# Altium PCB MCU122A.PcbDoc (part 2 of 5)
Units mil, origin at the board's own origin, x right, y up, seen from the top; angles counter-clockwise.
Board outline 4950 x 3450 mil, 4 copper layers (Top Layer, Signal Layer 1, Signal Layer 2, Bottom Layer), stack 60 mil thick; 257 components, 158 nets, 848 pads, 1971 vias.
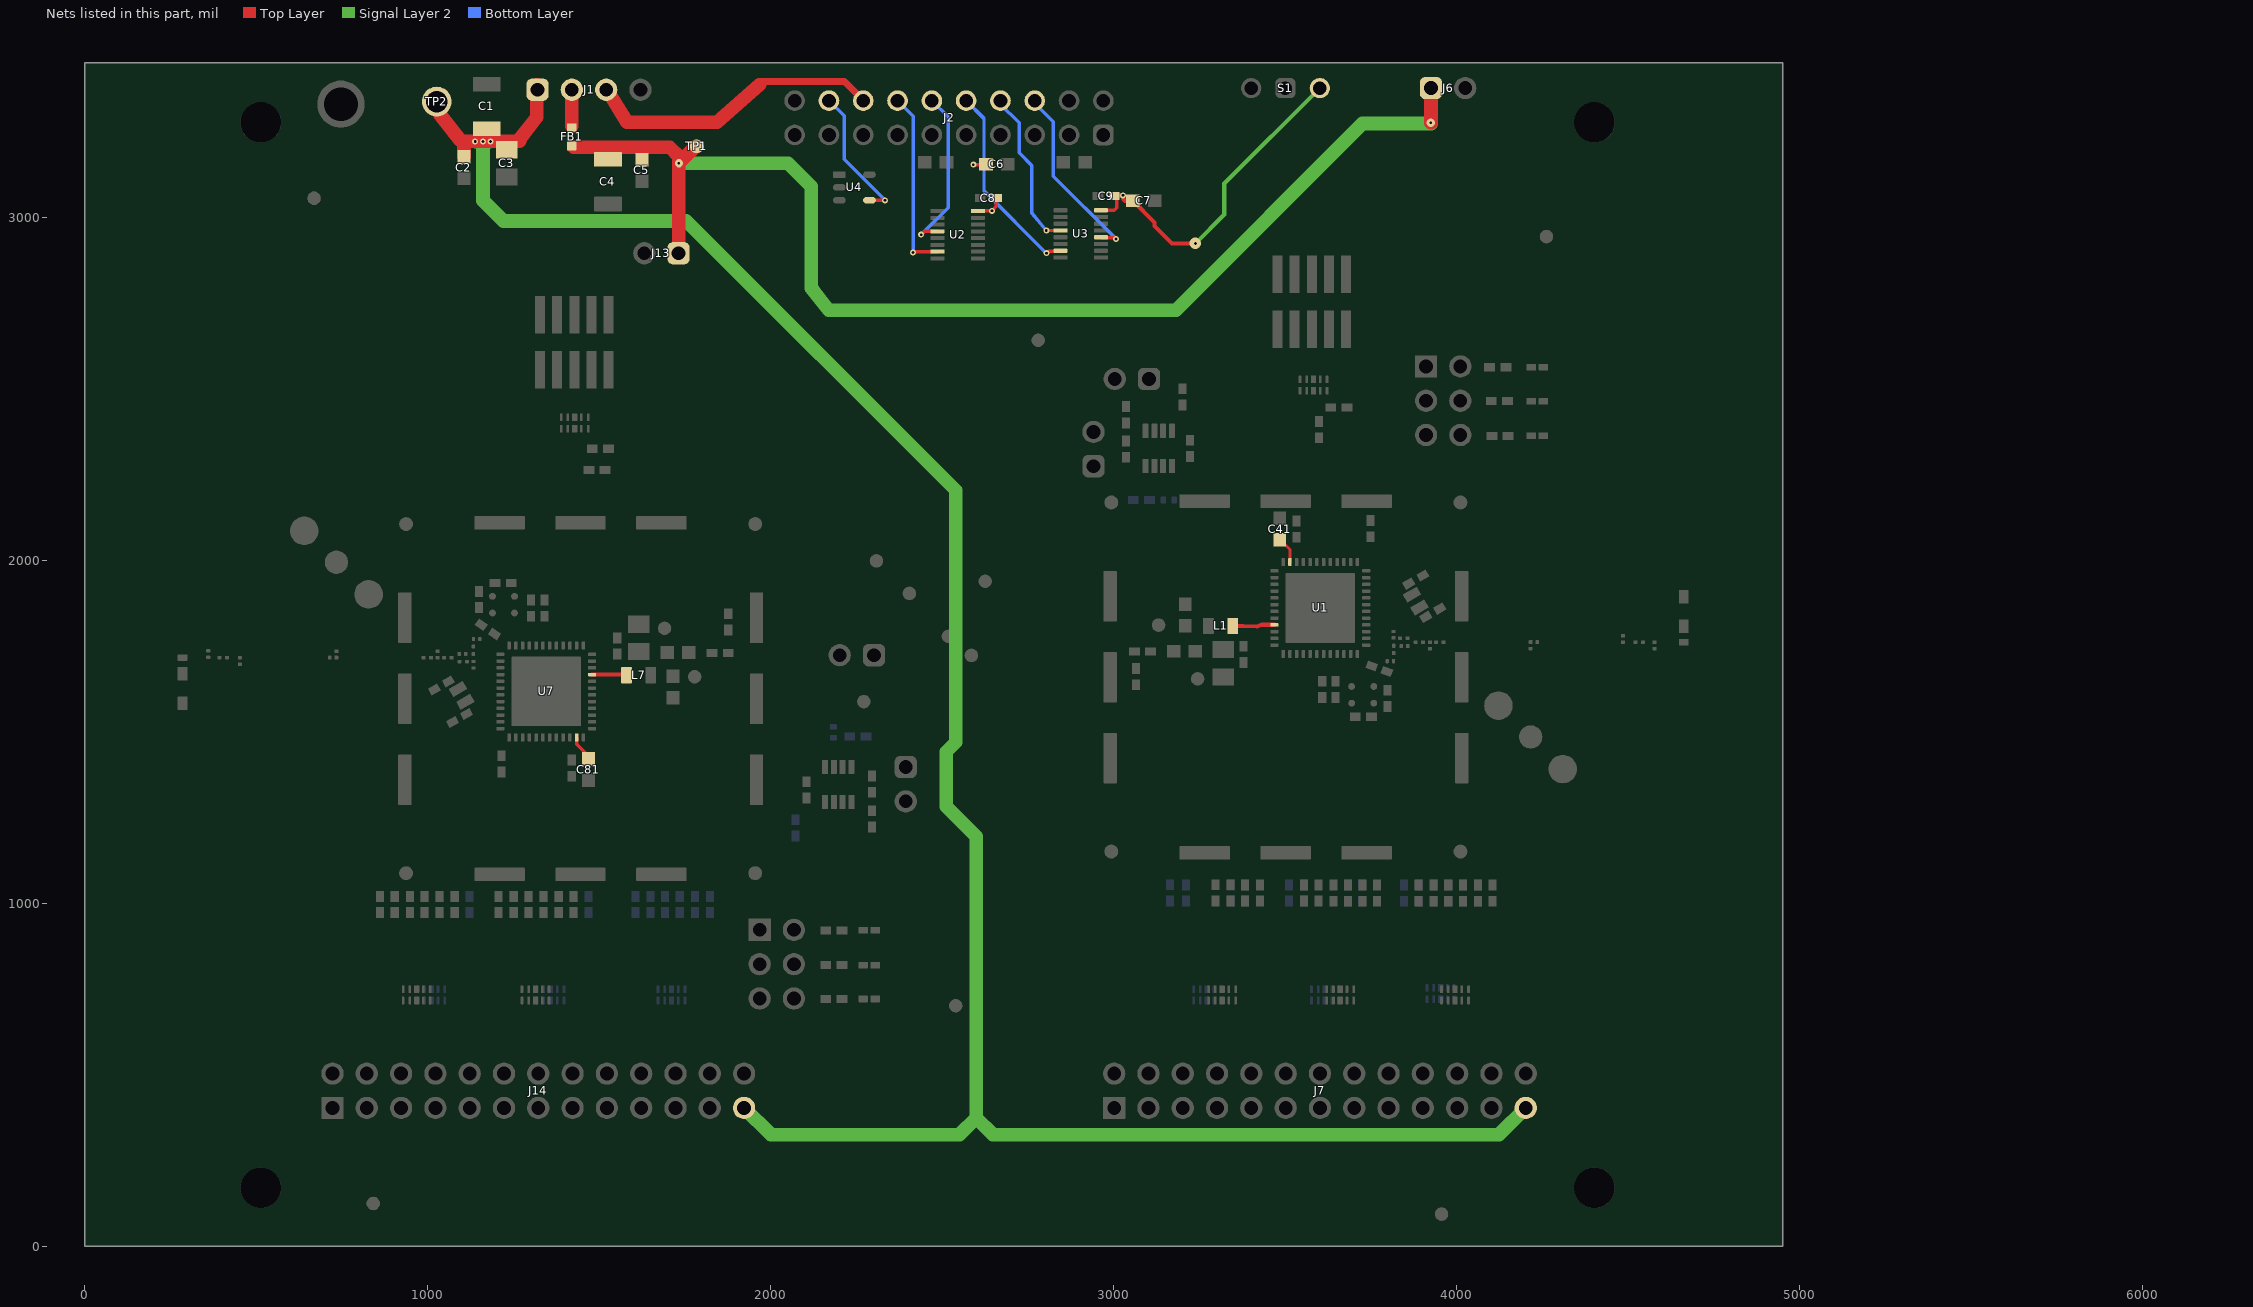
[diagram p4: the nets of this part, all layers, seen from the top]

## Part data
ANT1 ANT2: library part CMP-0091830-1, "2.4-GHz Inverted F Antenna", Manufacturer="Texas Instruments", Operating Temperature Range=to
C1 C4: library part CMP-0037171-1, "Ceramic Capacitor for Automotive 10uF ±20% 25VDC X7R 1210 Embossed T/R", Manufacturer=Murata, Operating Temperature Range="-55°C to +125°C", TempCo=15%, Temperature Characteristic=X7R, Tolerance_%=20%, ValueDisplayed=10uF
C2 C5 C6 C7 C10 C11 C41 C81: library part CMP-0007136-5, "CAP, CERM, 1 uF, 16 V, +/- 10%, X7R, AEC-Q200 Grade 1, 0603", Cap_Case=0603, Manufacturer=MuRata, Supplier Part Number 1=490-5241-6-ND, TempCo=X7R, Tolerance_%=10%, Value1=Unknown, Value2=16V, ValueDisplayed=1uF
C3 C21 C61: library part CMP-0008015-1, "CAP, CERM, 22 uF, 6.3 V, +/- 20%, X7T, AEC-Q200 Grade 1, 0805", Cap_Case=0805, Manufacturer=MuRata, TempCo=X7T, Tolerance_%=20%, Value1=Unknown, Value2=6.3V, ValueDisplayed=22uF
C8 C9 C22 C23 C24 C25 C27 C28 C48 C50 C62 C63 C64 C65 C67 C68 C88 C90: library part CMP-0006350-2, "CAP, CERM, 0.1 uF, 10 V, +/- 10%, X7R, AEC-Q200 Grade 1, 0402", Cap_Case=0402, Manufacturer=MuRata, Supplier Part Number 1=81-GCM155R71A104K5D, TempCo=X7R, Tolerance_%=10%, Value1=Unknown, Value2=10V, ValueDisplayed=0.1uF
C12 C13 C14 C15 C16 C17 C18 C19 C20 C29 C30 C31 C32 C33 C34 C52 C53 C54 C55 C56 C57 C58 C59 C60 C69 C70 C71 C72 C73 C74: library part CMP-0006350-2, "CAP, CERM, 0.1 uF, 10 V, +/- 10%, X7R, AEC-Q200 Grade 1, 0402", Cap_Case=0402, Manufacturer=MuRata, Supplier Part Number 1=81-GCM155R71A104K5D, TempCo=X7R, Tolerance_%=10%, Value1=Unknown, Value2=10V, ValueDisplayed=DNP
C26 C66: library part CMP-0064940-5, "CAP, CERM, 22 uF, 4 V,+/- 20%, X5R, AEC-Q200 Grade 3, 0603", Cap_Case=0603, Manufacturer="Taiyo Yuden", Supplier Part Number 1=587-3262-1-ND, TempCo=X5R, Tolerance_%=20%, Value1=Unknown, Value2=4V, ValueDisplayed=22uF
C35 C36 C75 C76: library part CMP-0085816-1, "CAP, CERM, 12 pF, 50 V,+/- 5%, C0G/NP0, AEC-Q200 Grade 1, 0402", Cap_Case=0402, Manufacturer=MuRata, TempCo=C0G/NP0, Tolerance_%=5%, Value2=50V, ValueDisplayed=12pF
C37 C38 C77 C78: library part CMP-0085816-1, "CAP, CERM, 12 pF, 50 V,+/- 5%, C0G/NP0, AEC-Q200 Grade 1, 0402", Cap_Case=0402, Manufacturer=MuRata, TempCo=C0G/NP0, Tolerance_%=5%, Value2=50V, ValueDisplayed=DNP
C39 C46 C79 C86: library part CMP-0037173-1, "1pF ±0.1pF 50V Ceramic Capacitor C0G 0201 (0603 Metric)", Manufacturer=Murata, Operating Temperature Range="-55°C to +125°C", TempCo=30ppm/°C, Temperature Characteristic=C0G, ValueDisplayed=DNP
C40 C43 C80 C83: library part CMP-0120430-1, "High Q Chip Multilayer Ceramic Capacitors for Automotive 12pF ±2% 50Vdc 0201", Manufacturer=Murata, Operating Temperature Range="-25°C to +125°C", TempCo=30ppm/°C, Temperature Characteristic=C0G, Tolerance_%=2%, ValueDisplayed=12pF
C42 C44 C47 C82 C84 C87: library part CMP-0120431-1, "1pF ±0.05pF 50V Ceramic Capacitor C0G 0201 (0603 Metric)", Manufacturer=Murata, Operating Temperature Range="-55°C to +125°C", TempCo=30ppm/°C, Temperature Characteristic=C0G, ValueDisplayed=1pF
C45 C85: library part CMP-0124488-1, "Cap Ceramic 0.7pF ±0.05pF 50V C0G 0201 AECQ200", Manufacturer=Murata, Operating Temperature Range="-55°C to +125°C", TempCo=30ppm/°C, Temperature Characteristic=C0G, ValueDisplayed=0.7pF
C49 C89: library part CMP-0120705-1, "Ceramic Capacitor for Automotive 47nF ±10% 25VDC X7R 0402 Paper T/R", Manufacturer=Murata, Operating Temperature Range="-55°C to +125°C", TempCo=15%, Temperature Characteristic=X7R, Tolerance_%=0.1%, ValueDisplayed=47nF
C51 C91: library part CMP-0006352-2, "CAP, CERM, 0.01 uF, 25 V, +/- 10%, X7R, 0402", Cap_Case=0402, Manufacturer=MuRata, Supplier Part Number 1=490-6043-2-ND, TempCo=X7R, Tolerance_%=10%, Value1=Unknown, Value2=25V, ValueDisplayed=0.01uF
D1 D4: library part CMP-0120353-1, "Green 525nm LED Indication - Discrete 2.65V 0402 (1005 Metric)", Color=Green, Digikey Part Number=754-2126-1-ND, Forward Current=2mA, Manufacturer=Kingbright, Mouser Part Number=604-APHHS1005LZGCK-V, Operating Temperature Range="-40°C to +85°C", Power_TotalModule=102.5mW
D2 D5: library part CMP-0120352-1, "LED Uni-Color SB. Orange 611nm 2-Pin SMD T/R", Color=Orange, Digikey Part Number=754-2124-1-ND, Forward Current=2mA, Manufacturer=Kingbright, Mouser Part Number=604-HHS1005LSECKJ4PF, Operating Temperature Range="-40°C to +85°C", Power_TotalModule=84mW
D3 D6: library part CMP-0120351-1, "Red 625nm LED Indication - Discrete 1.8V 0402 (1005 Metric)", Color=Red, Digikey Part Number=754-2123-1-ND, Forward Current=2mA, Manufacturer=Kingbright, Mouser Part Number=604-APHHS1005LSECKJ3, Operating Temperature Range="-40°C to +85°C", Power_TotalModule=84mW
FB1: library part CMP-0092703-1, "Chip Ferrite Bead, 0603, 1500Ω @ 100MHz, 0.5Ω, 25%, 500mA", Impedance At Frequency="1500Ω @ 100MHz", Manufacturer=Murata, Operating Temperature Range="-55°C to +125℃", Test Frequency=100MHz, Tolerance_%=25%
FB2 FB3: library part CMP-0080768-1, "Ferrite Bead, 1500 ohm @ 100 MHz, 0.5 A, 0603", Manufacturer=MuRata, Supplier Part Number 1=490-16502-1-ND, Value1="0.5 ohm", Value2=0.5A, ValueDisplayed="1500 ohm"
FID1 FID2 FID3 FID4 FID5 FID6 FID7 FID8 FID9 FID10 FID11 FID12: library part CMP-0077181-1, "Fiducial mark.  There is nothing to buy or mount.", Manufacturer=N/A
J1: library part CMP-0075409-2, "Header, 100mil, 4x1, Gold, TH", Color=Black, Current_A=6.3A, Manufacturer=Samtec, Supplier Part Number 1=SAM1029-04-ND, Voltage_V=550V
J2: library part CMP-0074634-1, "Receptacle, 2.54mm, 10x2, Gold, R/A, TH", Color=Black, Current_A=3A, Manufacturer="Sullins Connector Solutions", Supplier Part Number 1=S9205-ND, Voltage_V=1kV
J3 J10: library part CMP-0075406-2, "Header, 100mil, 3x2, Gold, TH", Color=Black, Current_A=6.3A, Manufacturer=Samtec, Supplier Part Number 1=SAM1028-03-ND, Voltage_V=550V
J4 J11: library part CMP-0035654-1, "SMA PCB Surface Mount Jack 50 Ohm", Dielectric Material=PTFE, Digikey Part Number=ARF2755-ND, Frequency_Fixed=18GHz, Manufacturer="Amphenol Connex", Mouser Part Number=523-132134-10, Operating Temperature Range="-65°C to +165°C"
J5 J12: library part CMP-0075670-2, "Header (Shrouded), 1.27mm, 5x2, Gold, SMT", Color=Black, Current_A=3.3A, Manufacturer=Samtec, Supplier Part Number 1=SAM8796-ND
J6 J8 J9 J13 J15 J16: library part CMP-0075405-3, "Header, 100mil, 2x1, Gold, TH", Color=Black, Current_A=6.3A, Manufacturer=Samtec, Supplier Part Number 1=SAM1029-02-ND, Voltage_V=550V
J7 J14: library part CMP-0075425-1, "Header, 100mil, 13x2, Gold, TH", Color=Black, Current_A=6.3A, Manufacturer=Samtec, Supplier Part Number 1=SAM1028-13-ND, Voltage_V=550V
L1 L7: library part CMP-0121210-1, "Shielded Multilayer Inductor 6.8uH ±20% 550mA 325mΩ AEC-Q200 SMD 0805", Manufacturer=TDK, Operating Temperature Range="-55°C to +125°C", Test Frequency=2MHz, Tolerance_%=20%
L2 L6 L8 L12: library part CMP-0090225-1, "Inductor 3.7nH, Size Code 0603 (0201), High Q, Wide Variation. AEC-Q200", Manufacturer=Murata, Operating Temperature Range="-55°C to +125°C", Self Resonant Frequency=6GHz, Test Frequency=500MHz, Tolerance_%=0.1nH
L3 L4 L9 L10: library part CMP-0037178-1, "Film type RF Inductor for Automotive 3.4nH ±0.1nH 450mA 0.25Ω 0201 (0603)", Manufacturer=Murata, Operating Temperature Range="-55°C to +125°C", Self Resonant Frequency=7GHz, Test Frequency=500MHz, Tolerance_%=0.1nH
L5 L11: library part CMP-0124484-1, "Film type RF Inductor for Automotive 1.9nH ±0.1nH 600mA 0.15Ω 0201 (0603)", Manufacturer=Murata, Operating Temperature Range="-55°C to +125°C", Self Resonant Frequency=12.5GHz, Test Frequency=500MHz, Tolerance_%=0.1nH
Logo1: library part CMP-0074838-1, "Texas Instrument Corporate Signature"
Logo3: library part CMP-0074847-1, "FCC_disclaimer"
Logo4: library part CMP-0074769-4, Manufacturer="Texas Instruments"
Logo5: library part CMP-0074840-1, "ESD Susceptible Symbol"
MP1 MP2: library part CMP-0086879-1, "RF SHIELD 1.034\" X 1.034\" SMD", Manufacturer="Leader Tech"
MP3 MP4: library part CMP-0120478-1, "RF Shield Cover 1.058\" (26.87mm) X 1.058\" (26.87mm) Non-Vented Surface Mount", Digikey Part Number=1798-1210-ND, Manufacturer="Leader Tech", Mouser Part Number=861-SMS-403C, Operating Temperature Range=to
MP5 MP6 MP7 MP8: library part CMP-0016301-1, "Spacer Support Nylon 66 Natural", Manufacturer="Kang Yang USA", Operating Temperature Range=to
R1 R2 R3 R4 R5 R6 R7 R8 R9 R13 R14 R15 R16 R17 R18 R25 R26 R27 R28 R29 R30 R31 R32 R33 R37 R38 R39 R40 R41 R42: library part CMP-0026822-3, "RES, 0, 5%, 0.063 W, AEC-Q200 Grade 0, 0402", Manufacturer=Vishay-Dale, Power_W=63mW, Supplier Part Number 1=541-0.0JCT-ND, TempCo="200 ppm/C", Tolerance_%=5%, Value2=0.063W, Value_Code=0000, ValueDisplayed=0
R10 R11 R12 R34 R35 R36: library part CMP-0026917-5, "RES, 3.0 k, 5%, 0.063 W, AEC-Q200 Grade 0, 0402", Manufacturer=Vishay-Dale, Power_W=63mW, Supplier Part Number 1=541-3.0KJCT-ND, TempCo="200 ppm/C", Tolerance_%=5%, Value2=0.063W, Value_Code=3k00, ValueDisplayed=3.0k
R19 R20 R21 R43 R44 R45: library part CMP-0080661-1, "RES, 100 k, 1%, 0.0625 W, AEC-Q200 Grade 0, 0402", Manufacturer="Yageo America", Power_W=62.5mW, Supplier Part Number 1=YAG3434CT-ND, TempCo="100 ppm/C", Tolerance_%=1%, Value2=0.0625W, Value_Code=100k
R22 R23 R24 R46 R47 R48: library part CMP-0077731-1, "RES, 10.0 k, 1%, 0.063 W, AEC-Q200 Grade 0, 0402", Manufacturer="Yageo America", Power_W=63mW, Supplier Part Number 1=YAG3436CT-ND, TempCo="100 ppm/C", Tolerance_%=1%, Value2=0.063W, Value_Code=10k0, ValueDisplayed=10.0k
S1: library part CMP-0078235-1, "Switch, SPDT, On-On, 0.5 A, 12 VDC, TH", CurrentRating_mA=500A, Manufacturer="NIDEC SEIMITSU"
SH-J1 SH-J2 SH-J3 SH-J4 SH-J5 SH-J6 SH-J7 SH-J8 SH-J9 SH-J10 SH-J11 SH-J12 SH-J13: library part CMP-0003623-3, "Shunt, 100mil, Gold plated, Black", Alternate Manufacturer=3M, Alternate PartNumber=969102-0000-DA, Manufacturer=Samtec, Supplier Part Number 1=SAM8858-ND
TP1 TP4 TP5 TP6 TP7 TP8 TP9 TP10 TP11 TP12 TP13: library part CMP-0003825-1, "1mm Test Point, SMT", Manufacturer=Any
TP2: library part CMP-0055149-2, "Test Point, Multipurpose, White, TH", Color=White, Manufacturer="Keystone Electronics", Supplier Part Number 1=36-5012-ND
TP3: library part CMP-0055121-1, "Terminal, Turret, TH, Triple", Manufacturer=Keystone, PartNumber=1598-2, Supplier Part Number 1=36-1598-2-ND
U1 U7: library part CMP-0121950-1, "Automotive qualified SimpleLink wireless MCU for use in wireless battery management systems", Digikey Part Number=296-CC2662R1FTWRGZRQ1CT-ND, Frequency_Fixed=48MHz, Manufacturer="Texas Instruments", Max Supply Voltage=3.63V, Min Supply Voltage=1.8V, Mouser Part Number=595-C2662R1FTWRGZRQ1, Operating Temperature Range="-40°C to +105°C"
U2 U3: library part CMP-0860151-2, "SN3257QDYYRQ1, DYY0016A (SOT-23-THIN-16)", Alternate Manufacturer="Texas Instruments"
U4: library part CMP-0087170-1, "8KB I2C SER EEPROM TSOT 23", Manufacturer="ON Semiconductor"
U5 U8 U10 U11 U12 U13 U14 U15 U16 U17 U18 U19 U20: library part CMP-0073599-3, "Automotive 4-Channel ESD Protection Solution for SuperSpeed (up to 5 Gbps) Interface, DQA0010A (USON-10)", Alternate Manufacturer="Texas Instruments"
U6 U9: library part CMP-0120735-1, "Automotive Nano IQ Precision Window Watchdog Timer", Manufacturer="Texas Instruments", Max Supply Voltage=6V, Min Supply Voltage=900mV, Nominal Supply Current=0.25uA, Operating Temperature Range="-40°C to +125°C", Output Voltage=0-6V
Y1 Y3: library part CMP-0121920-1, "SMD Tuning Fork Crystal Resonators / kHz Band Crystal Resonators 32.768KHZ 7PF ±20PPM", Frequency Tolerance=20ppm, Frequency_Fixed=32.768kHz, Load Capacitance=7pF, Manufacturer=DAISHINKU, Operating Temperature Range="-40°C to +125°C"
Y2 Y4: library part CMP-0121714-1, "Quartz Crystal 48 MHz 7pF 10ppm", Frequency Stability=20ppm, Frequency Tolerance=10ppm, Frequency_Fixed=48MHz, Load Capacitance=7pF, Manufacturer="KYOCERA AVX", Operating Temperature Range="-40°C to +105°C"
ZZ1: library part CMP-0077236-1
ZZ2: library part CMP-0077237-1
ZZ3: library part CMP-0077238-1
ZZ4: library part CMP-0077238-1, "These assemblies must comply with workmanship standards IPC-A-610 Class 2, unless otherwise specified."

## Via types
v1: diameter 17.46, hole 8, Top Layer to Bottom Layer, tented both sides, 1708 vias
v2: diameter 13.9, hole 8, Top Layer to Bottom Layer, tented both sides, 206 vias
v3: diameter 19.68, hole 8, Top Layer to Bottom Layer, tented both sides, 42 vias
v4: diameter 24, hole 8, Top Layer to Bottom Layer, tented both sides, 8 vias
v5: diameter 19.46, hole 8, Top Layer to Bottom Layer, tented both sides, 6 vias
v6: diameter 34, hole 8, Top Layer to Bottom Layer, tented both sides, 1 vias

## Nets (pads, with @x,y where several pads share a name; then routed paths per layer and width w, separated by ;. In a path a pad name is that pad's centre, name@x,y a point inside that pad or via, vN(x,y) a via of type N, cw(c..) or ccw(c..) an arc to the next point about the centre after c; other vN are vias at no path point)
3V3_EXT: C1.2 C2.1 C3.1 J1.1 J7.25 J14.25 TP2.1 | length 6721.3
  Top Layer w40: TP2.1@1013.67,3320.99 1029.41,3320.99 1035.5,3314.9 1035.5,3299.15 1094.09,3224.5 ; C2.1@1105.83,3175.93 1105.98,3176.08 1105.98,3221.29 1140.4,3221.22 1161.42,3221.18 1172.26,3221.16 v1@1180.4,3221.14 ; v1@1181.1,3221.35 1224.5,3221.35 1267.9,3221.35 ; 1266.12,3224.5 1317.9,3291.35 J1.1@1317.9,3385.83
  Signal Layer 2 w40: v1@1140.4,3220.57 v1(1161.42,3220.57) v1@1181.1,3220.57 ; v1@1161.42,3218.8 1161.42,3048.21 1220.89,2988.74 1753.92,2988.74 2539.37,2203.29 2539.37,1468.84 2511.74,1441.2 2511.74,1281.69 2599.19,1194.24 2599.19,373.25 ; J14.25@1922.44,402.76 2000.39,324.8 2550.74,324.8 2599.19,373.25 ; J7.25@4201.38,402.76 4123.42,324.8 2647.64,324.8 2599.19,373.25
  other v1: 1138.4,3220.57 1183.1,3220.57
3V3_VDD: C4.2 C5.1 FB1.2 J6.1 J13.1 TP1.1 | length 3548.2
  Top Layer w10: J6.1@3924.8,3375.98 J6.1@3924.8,3399.6
  Top Layer w40: FB1.2@1425.49,3203.35 1705.88,3203.35 1732.28,3176.95 v4(1732.28,3156.96) ; J13.1@1732.28,2917.27 v4(1732.28,3156.96) ; TP1.1@1783.98,3205.93 1781.26,3205.93 v4(1732.28,3156.96) ; v4(3924.64,3274.66) 3924.8,3274.82 J6.1@3924.8,3375.98
  Signal Layer 2 w40: v4(1732.28,3156.96) 2050.39,3156.96 2118.2,3089.15 2118.2,2792.06 2123.21,2787.04 2169.15,2728.33 3181.37,2728.33 3725.53,3272.49 v4@3924.8,3272.49
3V3_WM: FB1.1 J1.2 | length 105.7
  Top Layer w40: FB1.1@1420.39,3265.45 J1.2@1420.39,3371.2
3V3_XDS: C6.2 C7.2 C8.2 C9.2 J1.3 J2.16 S1.3 U2.16 U3.16 | length 1988.2
  Top Layer w10: v1(2590.63,3152.58) C6.2@2637.56,3152.58 ; U2.16@2604.02,3017.41 2604.73,3018.12 v1(2645.36,3018.12) 2658.23,3030.99 C8.2@2658.23,3055.07 ; U3.16@2952.99,3019.86 U3.16@2962.88,3019.86 2997.53,3019.86 ; 3002.02,3019.86 3008.75,3026.59 C9.2@3008.75,3053.31
  Top Layer w12: C9.2@3001.63,3060.88 3004,3063.25 v1(3027.18,3063.25) 3027.18,3053.31 3032.9,3047.58 C7.2@3056.11,3047.58 3119.39,2984.3 3119.39,2974.25 3170.42,2923.22 v6(3238.18,2923.22)
  Top Layer w20: 1969.99,3395 2214.61,3395 J2.16@2269.88,3339.36
  Top Layer w40: J1.3@1520.44,3374.48 1521.89,3372.12 1580.79,3276.34 1843.49,3276.34 1967.45,3385.83
  Signal Layer 2 w12: v6(3238.18,2923.22) 3322.39,3007.43 3322.39,3097.47 S1.3@3600.9,3375.98
5V0_BP: J2.18 U4.4 | length 406.1
  Top Layer w10: U4.4@2288.01,3049.04 2288.09,3048.96 2333.51,3048.96 v1(2333.59,3048.88)
  Bottom Layer w10: J2.18@2169.88,3339.36 2214.42,3294.82 2214.42,3282.56 2214.11,3231.49 2214.11,3168.36 v1(2333.59,3048.88) v1@2333.59,3050.9
BCU_RESET: J2.10 U3.7 | length 585.8
  Top Layer w10: v1(2803.76,2894.48) 2810.13,2900.85 2843.86,2900.85 U3.7@2844.77,2901.75
  Bottom Layer w10: J2.10@2569.88,3339.36 2621.9,3287.34 2621.9,3076.34 v1(2803.76,2894.48)
BCU_RXD: J2.14 U2.7 | length 532.8
  Top Layer w10: v1(2415.24,2896.96) 2417.26,2896.96 2419.6,2899.3 U2.7@2485.91,2899.3
  Bottom Layer w10: J2.14@2369.88,3339.36 2415.24,3294.01 v1(2415.24,2896.96)
BCU_SWDCK: J2.6 U3.12 | length 549.4
  Top Layer w10: U3.12@2962.88,2941.12 2963.78,2940.22 3002.86,2940.22 v1(3006.78,2936.3)
  Signal Layer 2 w10: v1(3006.78,2936.3) v1@3009.09,2936.3
  Bottom Layer w10: J2.6@2769.88,3339.36 2769.88,3331.7 2824.1,3277.48 2824.1,3118.98 v1(3006.78,2936.3)
BCU_SWDIO: J2.8 U3.4 | length 473.4
  Top Layer w8: v1(2803.44,2960.81) U3.4@2844.77,2960.81
  Signal Layer 2 w10: v1(2803.44,2960.81) v1@2803.76,2961.13
  Bottom Layer w10: J2.8@2669.88,3339.36 2669.88,3329.1 2724.1,3274.89 2724.1,3187.76 2761.5,3150.36 2761.5,3011.51 v1(2803.44,2960.81)
BCU_TXD: J2.12 U2.4 | length 514.7
  Top Layer w10: v1(2438.67,2948.51) 2448.51,2958.36 U2.4@2485.91,2958.36
  Signal Layer 2 w10: J2.12@2473.31,3343.66 2474.34,3341.62 J2.12@2482.46,3325.58
  Bottom Layer w10: v1(2438.67,2948.51) 2448.51,2958.36 2517.41,3027.25 2517.41,3291.84 J2.12@2469.88,3339.36
DCDC_SW_WM1: L1.1 U1.33 | length 149.8
  Top Layer w10: L1.1@3349.85,1808 3377.89,1808 3379.5,1806.39
  Top Layer w12: L1.1@3349.85,1808 3417.68,1806.39 3432.25,1811.5 U1.33@3468.5,1811.5
DCDC_SW_WM2: L7.1 U7.33 | length 102.1
  Top Layer w10: L7.1@1576.61,1664.38 L7.1@1576.61,1668.6
  Top Layer w11: L7.1@1574.9,1666.09 L7.1@1576.61,1664.38
  Top Layer w12: U7.33@1479.43,1666.09 L7.1@1574.9,1666.09
DCOUPL_WM1: C41.1 U1.23 | length 79.1
  Top Layer w8: C41.1@3484.17,2060.01 3513.78,2030.4 U1.23@3513.78,1994.09 U1.23@3514.7,1994.09
DCOUPL_WM2: C81.1 U7.23 | length 76.8
  Top Layer w10: U7.23@1434.16,1483.02 1434.16,1463.33 1468.5,1428.99 C81.1@1468.5,1420.5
